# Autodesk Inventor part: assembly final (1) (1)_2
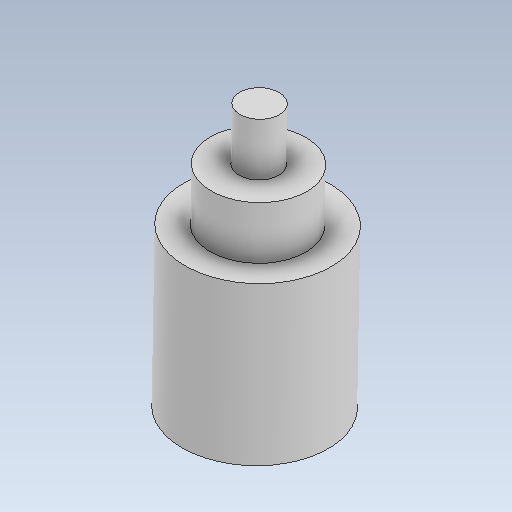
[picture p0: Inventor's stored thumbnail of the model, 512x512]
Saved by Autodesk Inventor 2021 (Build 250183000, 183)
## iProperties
Created: 2021-07
Part Number: assembly final (1) (1)_2
Material: Generic
Document SubType Name: Modeling
Designer: TARUN
Density: 1 g/cm^3
Appearance: Default
Author: TARUN
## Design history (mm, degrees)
feature "Base1"
body "Solid1"
